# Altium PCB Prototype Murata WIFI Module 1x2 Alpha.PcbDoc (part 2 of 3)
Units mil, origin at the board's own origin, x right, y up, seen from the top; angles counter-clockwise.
Board outline 708.66 x 1594.49 mil, 6 copper layers (Component Side, Ground Plane (GND), Inner Layer 1, Inner Layer 2, Power Plane (VCC), Solder Side), stack 20.279 mil thick; 197 components, 116 nets, 943 pads, 479 vias.
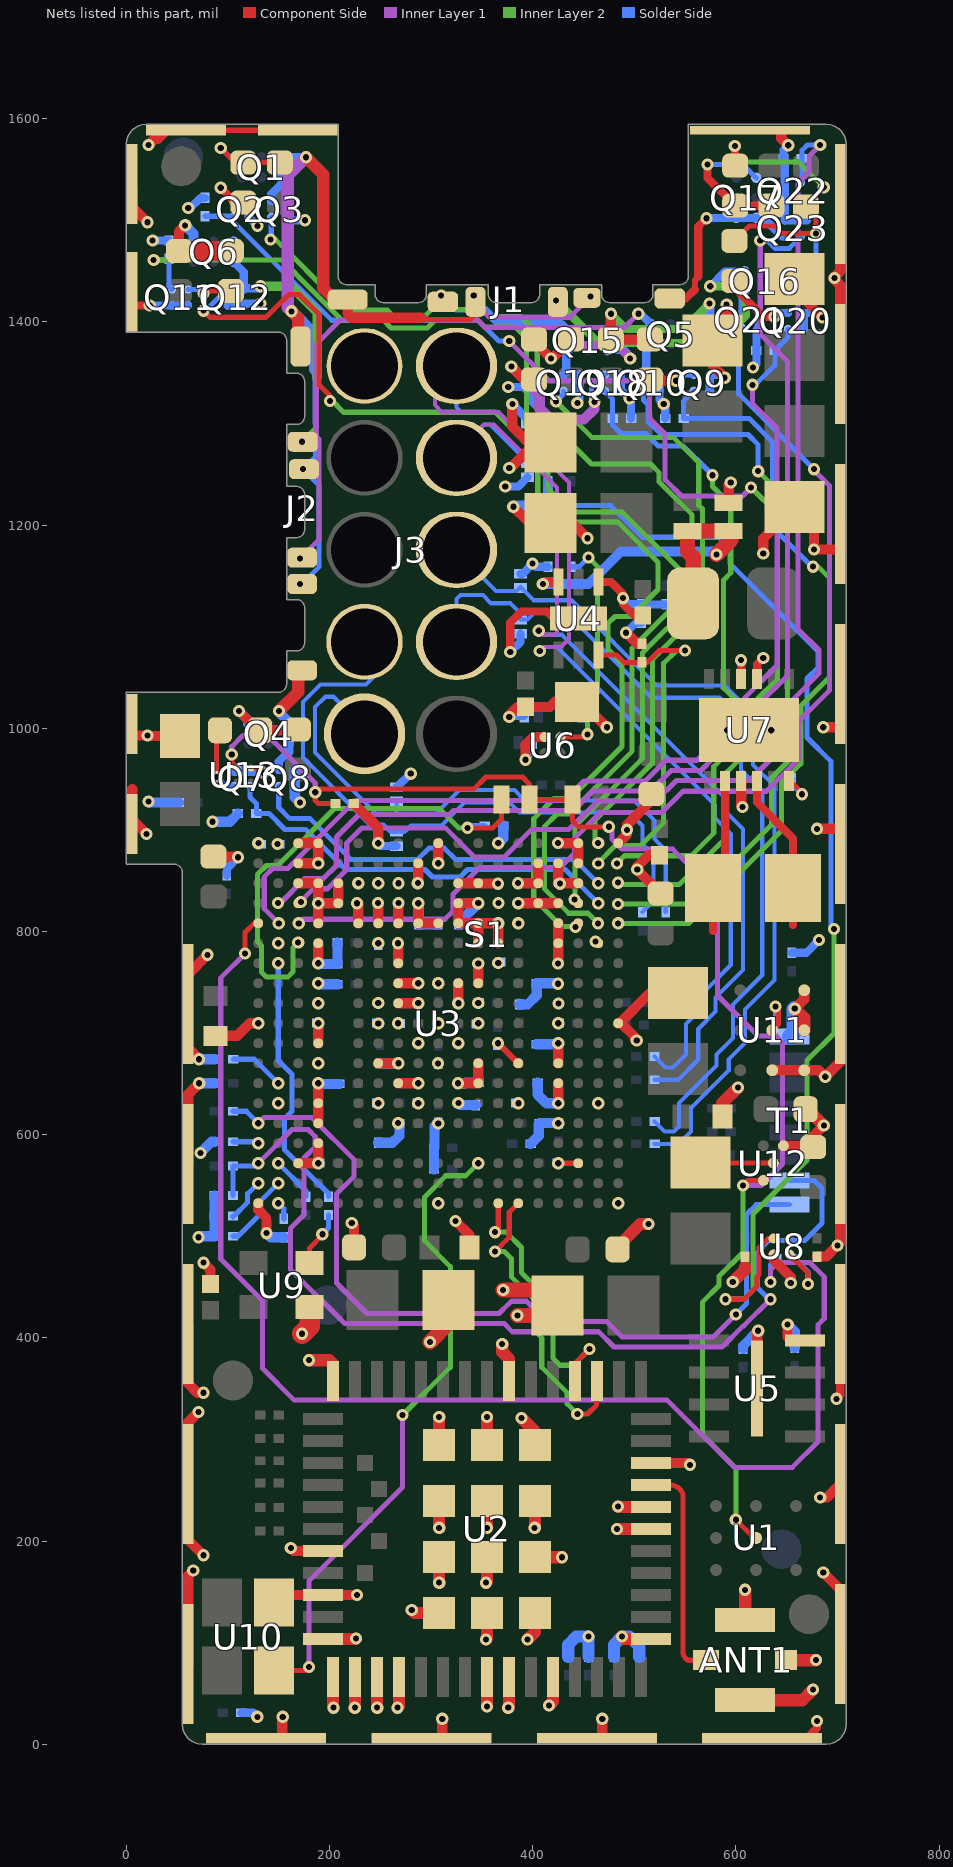
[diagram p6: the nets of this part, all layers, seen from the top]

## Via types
v1: diameter 12, hole 6, Component Side to Solder Side, tented both sides, 479 vias

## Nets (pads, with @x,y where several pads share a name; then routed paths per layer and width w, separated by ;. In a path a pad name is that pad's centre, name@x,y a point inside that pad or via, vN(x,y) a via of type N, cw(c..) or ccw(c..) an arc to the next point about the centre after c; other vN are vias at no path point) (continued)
C_RX_N: C49.1 J3.2 TVS6.1 | length 603.7
  Solder Side w4: J3.2@234.53,994.4 234.53,1000.47 204,1031 196,1031 186,1021 186,976 238.5,923.5 246,916 266,916 ; TVS6.1@266,928.01 266,916 ; C49.1@531,819.06 531,879.97 520,890.97 520,909 500,929 392,929 382,939 328,939 305,916 266,916
C_RX_P: C48.1 J3.4 TVS5.1 | length 653
  Solder Side w4: J3.4@234.53,1084.95 244,1075.47 244,1051 236,1043 191.03,1043 174,1025.97 174,971.03 240.03,905 253,905 260.01,897.99 TVS5.1@266,897.99 273.99,897.99 280.01,904.01 ; 280.03,904 309.97,904 332.97,927 377.03,927 387.03,917 495.03,917 508,904.03 508,886 519,875 519,830 C48.1@508.06,819.06
C_TX_CLK_N: C47.1 J3.7 R15.1 R37.1 TVS4.1 | length 1105.7
  Inner Layer 1 w4: J3.7@325.08,1266.05 325.08,1272.08 352,1299 362.03,1299 424,1237.03 424,1094 ; v1(406,1096) 410,1092 422,1092 424,1094 ; 424,1162 424,1094
  Solder Side w4: J3.7@325.08,1266.05 325.08,1272.08 352,1299 358,1299 395,1262 TVS4.1@395,1260.99 414.93,1260.99 R37.1@415,1261.06 R15.1@438,1261.06 ; v1(406,1096) 410,1092 428.97,1092 591.49,929.49 591.49,916.49 607,900.97 607,762.03 580,735.03 580,721 563,704 563,674 543,654 525.94,654 C47.1@519.91,654
C_TX_CLK_P: C46.1 J3.9 R36.1 R62.1 TVS3.1 | length 1115
  Inner Layer 1 w4: J3.9@325.08,1356.6 304,1335.53 304,1318 311,1311 367,1311 436,1242 436,1088 428,1080 411,1080 v1(407,1076)
  Solder Side w4: J3.9@325.08,1356.6 325.08,1315.92 330,1311 362.97,1311 387.96,1286.01 TVS3.1@395,1286.01 404.93,1286.01 406,1284.94 R62.1@415,1284.94 R36.1@438,1284.94 ; v1(407,1076) 411,1080 424,1080 579.49,924.51 579.49,911.51 583,908 595,896 595,767 568,740 568,725.97 551,708.97 551,678.97 538.03,666 530.91,666 C46.1@519.91,677
C_TX_N: C45.1 J3.3 TVS2.1 | length 857.4
  Solder Side w4: J3.3@325.08,1084.95 325.08,1127.08 329,1131 351,1131 359,1123 378,1123 388,1113 TVS2.1@388,1106.99 394.99,1106.99 402,1114 433.03,1114 517.03,1030 584,1030 605,1009 605,959 626,938 626,756.97 597,727.97 597,695 581,679 581,668 544,631 544,607.97 539.03,603 530,603 C45.1@520,613
C_TX_P: C43.1 J3.5 TVS1.1 | length 857.6
  Solder Side w4: J3.5@325.08,1175.5 325.08,1173.92 364,1135 383.99,1135 388,1139.01 401.01,1126 438,1126 522,1042 588.97,1042 617,1013.97 617,963.97 638,942.97 638,752 609,723 609,690.03 593,674.03 593,663.03 556,626.03 556,603 544,591 C43.1@520.09,591
CLK_19P2MHZ: R52.2 U3.N18 | length 256.2
  Solder Side w5: v1(149.61,768.7) 149.61,672.99 163.11,659.49 163.11,623 155.79,615.69 155.79,585.1 182.72,558.17 182.83,558.17 199,542 R52.2@199,539.06
CLK_REQ: U2.4 U3.A7 | length 267.2
  Component Side w5: v1(363,504) 366.14,507.14 U3.A7@366.14,532.48 ; U2.4@442,357.28 U2.4@441.61,357.67 441.61,374.61 v1(456,389)
  Inner Layer 2 w5: v1(363,504) 374,504 389,489 389,464.14 416.5,436.64 416.5,422.65 420,419.15 420,380 427,373 440,373 v1(456,389)
DETECT_RX: R69.2 U3.R19 | length 1336.2
  Component Side w5: v1(116.85,778.15) 116.85,798.85 126.07,808.07 U3.R19@129.92,808.07
  Inner Layer 1 w5: v1(116.85,778.15) 93,754.3 93,477.57 134,436.57 134,370 165,339 532,339 598.5,272.5 655.5,272.5 681,298 681,413 687,419 687,460 673,474 641,474 634,467 v1(634,455) v1@634,454
  Solder Side w5: v1@634,454 v1(634,455) 634,472.06 R69.2@639.94,478
DONE: R34.1 T1.8 U3.E19 | length 855.2
  Inner Layer 1 w5: v1(129.92,611.22) 135.6,616.9 182.7,616.9 224.3,575.3 224.3,559 207,541.7 207,454 237,424 367,424 376.5,433.5 ; 376.59,433.5 379.09,436 393.86,436 413.86,416 473,416 488,401 578,401 v1(600,423)
  Solder Side w5: R34.1@105.06,623 118.14,623 v1(129.92,611.22) ; v1(600,423) 610.5,433.5 610.5,521.5 620.1,531.1 T1.8@652.76,531.1
EN_32KHZ_CLK: U3.C8 U10.1 | length 633.3
  Component Side w5: U10.1@145.59,72.54 176.54,72.54 v1(180,76)
  Inner Layer 1 w5: v1(180,76) 180,161 272,253 v1(272,324)
  Inner Layer 2 w5: v1(272,324) 319,371 319,470 293.5,495.5 293.5,538.5 314.5,559.5 334.11,559.5 v1(346.46,571.85)
EPM_HBA_N: Q3.1 U3.T3 | length 1040.2
  Component Side w5: U3.T3@441.67,830.97 U3.T3@444.88,827.76
  Inner Layer 2 w5: v1(142,1480.92) 147.23,1480.92 177,1451.14 177,1451 216.5,1411.5 257.27,1411.5 264.77,1404 292.19,1404 300.19,1412 349.96,1412 356.96,1405 389,1405 404.5,1389.5 404.5,1313.5 458,1260 516,1260 524.5,1251.5 524.5,1242.41 532.41,1234.5 532.5,1234.5 557,1210 557,1123 508,1074 508,970 441.67,903.67 441.67,831 v1(441.2,831.44)
  Solder Side w5: v1(142,1480.92) 142.08,1480.92 142.72,1480.28 142.72,1488.85 ; Q3.1@142.72,1502.56 Q3.1@142.72,1503.13 ; 142.75,1488.88 142.75,1502.53 Q3.1@142.72,1503.13
EPM_HBA_P: Q2.1 R12.1 U3.U1 | length 1201.3
  Inner Layer 1 w5: v1(377,1381) 416,1342 503,1342 515,1330 515,1305 530.45,1289.55 530.45,1244.55 546.5,1228.5 606.5,1228.5 v1(615,1237)
  Inner Layer 2 w5: v1(484,848) 486,846 544,846 591,893 591,956.66 621.34,987 621.34,1028.7 640.82,1048.18 640.82,1211.18 v1(615,1237)
  Solder Side w5: R12.1@77.38,1503.94 104.06,1503.94 Q2.1@104.88,1503.13 104.88,1498.94 202.22,1401.6 346.22,1401.6 366.82,1381 v1(377,1381)
EPM_HBB_N: Q8.1 U3.U2 | length 375.6
  Solder Side w5: Q8.1@150.13,943.13 150.13,921.87 161,911 181,911 221,871 287,871 298,882 313,882 324,871 441.01,871 v1(464.57,847.44)
EPM_HBB_P: Q7.1 R41.1 U3.T2 | length 408.6
  Solder Side w5: Q7.1@121.87,943.13 121.87,932.18 128.06,926 R41.1@128.06,916 140.67,916 156.33,900.34 176.66,900.34 216.03,860.97 222.79,860.97 ; 222.81,861 294,861 301.37,853.63 328.63,853.63 336,861 432.09,861 440.5,852.59 ; 440.5,851.82 v1(464.57,827.76)
EPM_HBC_N: Q10.1 U3.T1 | length 725.8
  Inner Layer 2 w5: v1(484,827) 557,827 635,905 635,951 650.82,966.82 650.82,1224.18 v1(622,1253)
  Solder Side w5: Q10.1@509.13,1332.13 509.13,1323 513.37,1318.75 513.37,1302.12 526.49,1289 612,1289 622,1279 v1(622,1253)
EPM_HBC_P: Q9.1 R42.1 U3.R1 | length 754.7
  Inner Layer 2 w5: v1(484.2,808) 554,808 645,899 645,946 664,965 664,1022 692,1050 692,1148 681,1159 v1(676,1159)
  Solder Side w5: Q9.1@558.53,1332.13 548.66,1322.25 548.66,1318.34 R42.1@548.66,1305 612.86,1305 635.93,1281.93 635.93,1197.98 v1@674.91,1159
EPM_HBD_N: Q12.1 U3.R3 | length 1129.9
  Component Side w5: v1(76,1411) 82.5,1404.5 137.59,1404.5 145.5,1412.41 160.09,1427 170,1427 189.62,1407.38 189.62,1338 200.5,1327.13 v1(200.5,1322)
  Inner Layer 2 w5: v1(200.5,1322) 203,1322 213.95,1311.05 255.67,1311.05 255.72,1311 303.89,1311 303.94,1311.05 363.45,1311.05 405,1269.5 405,1231 433,1203 483.86,1203 522.93,1163.93 522.93,1163.73 523.5,1163.16 523.5,1136.5 497,1110 481,1110 474,1103 474,1078 488,1064 488,982 436.87,930.87 421,930.87 401.08,910.95 401.08,832.43 428.51,805 v1@442.28,805
  Solder Side w5: v1@78.09,1411 98.97,1431.87 Q12.1@99.89,1431.87
  other v1: 442.28,804.44
EPM_HBD_P: Q11.1 R44.1 U3.R2 | length 1214.7
  Inner Layer 2 w5: v1(27,1461) 153,1461 167,1447 167,1446.86 212.35,1401.5 253.12,1401.5 260.63,1394 296.34,1394 304.34,1402 345.82,1402 352.82,1395 383,1395 394,1384 394,1326 394,1297 415,1276 415,1235.91 437.91,1213 488,1213 544,1157 544,1125 498,1079 498,977.44 436.06,915.5 424,915.5 411.51,903.01 411.51,842 435.56,817.94 454.4,817.94 v1(464.34,808)
  Solder Side w5: v1(27,1461) 41.06,1461 R44.1@42,1461.94 42,1435.01 Q11.1@45.14,1431.87
EPM_HBE_N: Q19.1 U3.W2 | length 595.6
  Inner Layer 2 w5: v1(423.03,1321.53) 458.56,1286 539,1286 563.5,1261.5 563.5,1219.5 567,1216 567,1117 518,1068 518,976 518,965.86 461.5,909.36 v1@461.5,890.01
  Solder Side w5: v1(423.03,1321.53) 430.38,1328.87 Q19.1@430.38,1332.13
  other v1: 464.51,887
EPM_HBE_P: Q18.1 R59.1 U3.V1 | length 639.1
  Inner Layer 2 w5: v1(483,867) 490.5,874.5 556,874.5 578.25,896.75 578.25,962.21 606,989.96 606,1021.34 588,1039.34 588,1146 595,1153 595,1220 577,1238 v1(577,1249)
  Solder Side w5: Q18.1@471.29,1332.13 471.29,1331.56 478.79,1324.06 R59.1@478.79,1305 478.79,1298.21 487,1290 511.35,1290 523.58,1277.77 548.32,1277.77 v1@573,1253.09
EPM_HBF_N: Q21.1 U3.R17 | length 1051.2
  Inner Layer 1 w5: v1(169.77,808) 173.77,812 313.59,812 321.59,820 321.59,836.59 348,863 427,863 441,877 441,891.18 466.82,917 527,917 548,938 630,938 662,970 662,1007 692,1037 692,1239 v1@677,1254
  Solder Side w5: Q21.1@606.44,1393.97 602.77,1390.3 602.77,1329.23 v1(677,1255)
EPM_HBF_P: Q20.1 R60.1 U3.R18 | length 1019.8
  Inner Layer 1 w5: v1(150.07,808) 135.86,822.21 135.86,853.77 144.05,861.95 158.95,861.95 226,929 431.44,929 450.64,948.2 511,948.2 531.3,968.5 561.5,968.5 574.7,981.7 594.3,981.7 609.16,996.56 609.16,1030.46 640.5,1061.8 640.5,1295.77 616.27,1320 v1(616.27,1338)
  Solder Side w5: v1(616.27,1338) 619.09,1338 638.37,1357.28 R60.1@638.37,1371.84 651.32,1384.79 Q20.1@651.32,1393.13
EPM_HBG_N: Q23.1 U3.T18 | length 1117.1
  Inner Layer 1 w5: v1(149.36,828) 151.73,828 175.73,852 194,852 207,865 207,893 229,915 318,915 322,919 440.14,919 459.34,938.2 516,938.2 536.3,958.5 565.64,958.5 578.14,971 602.11,971 621.11,990 621.11,1022.11 651,1052 651,1360.86 624,1387.86 v1(624,1480)
  Solder Side w5: v1(624,1480) 631,1480 638.66,1472.34 652.66,1472.34 663.87,1483.56 Q23.1@663.87,1484.13
EPM_HBG_P: Q22.1 R61.1 U3.T17 | length 1254.9
  Inner Layer 1 w5: v1(171.82,829) 171.82,829.69 184.13,842 198.14,842 217,860.86 217,887 232,902 314,902 342.64,873.36 372,873.36 399.14,900.5 435.78,900.5 463.48,928.2 521.2,928.2 541.5,948.5 613.5,948.5 652,987 652,1024 682,1054 682,1077 661,1098 661,1536 671.84,1546.84 671.84,1562.84 v1(683,1574)
  Solder Side w5: Q22.1@663.87,1536.87 665.06,1538.06 R61.1@665.06,1561 665.06,1568.94 665.29,1568.94 670.34,1574 v1(683,1574)
EPM_REG_EN: R16.1 U3.V2 U4.6 | length 357.1
  Component Side w5: U4.6@464.69,1072.17 482.83,1072.17 490.11,1064.89 R16.1@507.63,1064.89 512.94,1064.89 524.62,1076.57 v1(550,1076.57)
  Inner Layer 2 w5: v1@464.57,867.66 481.41,884.5 506.5,884.5 529,907 529,1064 541.57,1076.57 v1(550,1076.57)
  other v1: 464.57,867
EPMA: J1.0 J2.0 Q1.4 Q1.5 Q3.4 | length 1019.4
  Component Side w5: 290.5,1404 292.3,1402.21 338.61,1402.21 343.72,1407.32 J1.0@343.72,1419.71
  Component Side w10: J1.0@205.2,1421.8 J1.0@216.22,1421.8 ; J1.0@217.94,1421.8 217.94,1408.07 222,1404 290.5,1404
  Component Side w12: v1(162.55,1410.36) 169.29,1403.62 J2.0@169.29,1375.74 ; v1(177,1562) 194,1545 194,1433 J1.0@203.77,1423.23
  Inner Layer 1 w5: v1(342,1426) 342,1419.96 357.46,1404.5 436.5,1404.5 v1(457,1425)
  Inner Layer 1 w12: v1(162.55,1410.36) 159,1413.91 159,1544 v1(177,1562)
  Solder Side w5: v1@173,1142 189.53,1158.53 189.53,1239.47 v1(174,1255) 186.5,1267.5 186.5,1299.5 186,1300 186,1353
  Solder Side w8: Q3.4@142.72,1518.87 142.72,1525.72 152.81,1535.81 Q1.4@152.81,1542.28 Q1.5@152.81,1561.97 v1(177,1562)
  Solder Side w12: v1(162.55,1410.36) 186,1386.91 186,1353
  other v1: 171,1142
EPMB: J2.3 Q4.4 Q4.5 Q8.4 | length 114.4
  Component Side w12: v1(150.47,1016.86) 169.29,1035.68 J2.3@169.29,1058
  Solder Side w8: Q8.4@150.13,958.87 150.13,967.13 159.69,976.69
  Solder Side w10: v1@150,1016.39 159.69,1006.7 Q4.5@159.69,1004.53 Q4.4@159.69,984.84 159.69,976.69
EPMC: J2.2 Q5.4 Q5.5 Q10.4 | length 624.9
  Inner Layer 1 w5: v1(171,1167) 189.53,1185.53 189.53,1284.69 187,1287.22 187,1378 211,1402 345.82,1402 353.32,1394.5 490.5,1394.5 v1(504,1408)
  Solder Side w8: v1(504,1408) 506.24,1408 Q5.4@516.4,1397.84 Q5.5@516.4,1378.16 511.84,1373.6 511.84,1366 511.84,1350.59 Q10.4@509.13,1347.87
EPMD: J2.1 Q6.4 Q6.5 Q12.4 | length 267.5
  Inner Layer 2 w5: v1(173,1282) 173,1282.31 187,1296.31 187,1344.38
  Inner Layer 2 w9: v1(132,1435) 161.89,1435 187.62,1409.26 187.62,1345
  Solder Side w8: Q6.5@105.6,1478.84 Q6.4@105.6,1459.16 115.63,1449.12 Q12.4@115.63,1431.87 116.76,1433 130,1433 v1(132,1435)
EPME: J1.1 Q15.4 Q15.5 Q19.4 | length 184.2
  Solder Side w5: v1(310,1426) 324.4,1411.6 353.4,1411.6
  Solder Side w8: 353.4,1411.6 367,1398 428.22,1398 Q15.4@434.38,1391.84 Q15.5@434.38,1372.16 433.09,1370.87 433.09,1350.59 Q19.4@430.38,1347.87
EPMF: J1.2 Q16.4 Q16.5 Q21.4 | length 352.9
  Inner Layer 2 w8: v1(423,1421) 465,1379 583,1379 610,1406 610,1422 597,1435 v1(574.81,1435)
  Solder Side w8: v1(574.81,1435) 589.49,1449.68 Q16.4@608.63,1449.68 Q16.5@608.63,1430 606.44,1427.81 Q21.4@606.44,1409.72
EPMG: J1.3 Q17.4 Q17.5 Q23.4 | length 187.9
  Component Side w6: 559.81,1432 559.81,1441.21 563,1444.41
  Component Side w8: J1.3@534.96,1423.23 551.03,1423.23 559.81,1432 ; 563,1444.41 563,1494 v1(571,1502)
  Solder Side w8: v1(571,1502) 571.31,1502.31 Q17.4@600.51,1502.31 Q17.5@620.19,1502.31 627.25,1502.31 645.44,1484.13 Q23.4@648.13,1484.13
EXO_DETECT_RX: R66.2 U8.A1 | length 1111.9
  Component Side w5: v1(589.96,438) 591,438 608,438 621,451 621,460.38 623,462.38 623,489 631.87,497.87 U8.A1@637.13,497.87
  Inner Layer 2 w5: v1(589.96,438) 608,438 617,447 617,522 670,575 670,673.09 696.5,699.59 v1(696.5,802.5)
  Solder Side w5: R66.2@438,1219.06 476.94,1219.06 508,1188 583.09,1188 594.5,1176.59 594.5,1162 681.11,1075.39 681.11,1060.11 670,1049 670,991 693.5,967.5 693.5,805.5 v1(696.5,802.5)
EXO_WAKE_RX: R65.2 U6.A1 | length 231.7
  Component Side w5: U6.A1@427.47,991.37 450.37,991.37 454,995 v1(454,994)
  Inner Layer 2 w5: v1(454,994) 454,1025 464,1035 464,1159 v1(455,1168)
  Solder Side w5: R65.2@438,1158.94 445.94,1158.94 v1(455,1168)
GND: ANT1.2 ANT1.3 ANT1.4 C1.1 C2.1 C3.1 C4.1 C5.1 C6.1 C7.1 C9.1 C10.1 C11.1 C12.2 C13.2 C14.2 C15.2 C16.1 C17.2 C18.1 C19.1 C20.1 C21.1 C22.1 C23.1 C24.1 C25.1 C26.1 C27.1 C28.1 C29.1 C30.1 C31.1 C32.1 C33.1 C34.1 C35.1 C36.1 C37.1 C38.1 C39.1 C40.1 C41.1 C42.1 C44.1 C50.1 C51.1 C52.1 C55.1 C56.1 C57.1 C58.1 C59.1 C60.1 C61.1 C62.1 C63.1 C64.1 C65.1 C66.1 C67.1 C68.1 C69.1 C70.1 C71.1 C72.1 C73.1 C74.1 C75.1 C77.1 C78.1 C81.1 C82.1 C94.1 C95.1 D2.1 J3.10 Q2.2 Q2.3 Q3.2 Q3.3 Q7.2 Q7.3 Q8.2 Q8.3 Q9.2 Q9.3 Q10.2 Q10.3 Q11.2 Q11.3 Q12.2 Q12.3 Q18.2 Q18.3 Q19.2 Q19.3 Q20.2 Q20.3 Q21.2 Q21.3 Q22.2 Q22.3 Q23.2 Q23.3 R10.1 R12.2 R14.2 R16.2 R20.1 R21.2 R23.2 R24.2 R25.2 R30.2 R32.2 R33.2 R37.2 R41.2 R42.2 R44.2 R47.2 R59.2 R60.2 R61.2 R62.2 R63.1 R67.2 R68.2 S1.S T1.1 TVS1.2 TVS2.2 TVS3.2 TVS4.2 TVS5.2 TVS6.2 TVS7.2 TVS8.2 TVS9.2 U2.7 U2.15 U2.22 U2.24 U2.26 U2.27 U2.28 U2.29 U2.30 U2.34 U2.35 U2.37 U2.42 U2.47 U2.48 U2.50 U2.53 U2.54 U2.55 U2.56 U2.57 U2.58 U2.59 U2.60 U2.61 U2.62 U2.63 U2.64 U3.A1 U3.A10 U3.A19 U3.C3 U3.C4 U3.C16 U3.C17 U3.D16 U3.E4 U3.E10 U3.E12 U3.E16 U3.F2 U3.F4 U3.F6 U3.F9 U3.F11 U3.F13 U3.F16 U3.F18 U3.G4 U3.G8 U3.G9 U3.G11 U3.G12 U3.G16 U3.H4 U3.H6 U3.H8 U3.H10 U3.H12 U3.H13 U3.H16 U3.J4 U3.J7 U3.J9 U3.J11 U3.J16 U3.K1 U3.K4 U3.K8 U3.K10 U3.K12 U3.K13 U3.K16 U3.K19 U3.L4 U3.L8 U3.L9 U3.L11 U3.L12 U3.L13 U3.L16 U3.M4 U3.M8 U3.M9 U3.M10 U3.M11 U3.M12 U3.M16 U3.N4 U3.N7 U3.N8 U3.N12 U3.N16 U3.P2 U3.P4 U3.P7 U3.P8 U3.P12 U3.P13 U3.P16 U3.P18 U3.R4 U3.R6 U3.R7 U3.R8 U3.R9 U3.R10 U3.R11 U3.R12 U3.R13 U3.R14 U3.R16 U3.T4 U3.T5 U3.T6 U3.T7 U3.T8 U3.T9 U3.T11 U3.T12 U3.T13 U3.T14 U3.T15 U3.T16 U3.U3 U3.U4 U3.U5 U3.U6 U3.U7 U3.U8 U3.U9 U3.U11 U3.U12 U3.U13 U3.U14 U3.U15 U3.U16 U3.U17 U3.V3 U3.V4 U3.V5 U3.V10 U3.V11 U3.V16 U3.V17 U3.W1 U3.W3 U3.W4 U3.W7 U3.W10 U3.W13 U3.W16 U3.W17 U3.W19 U4.7 U5.4 U5.9 U6.B1 U7.3 U7.9 U7.10 U7.13 U8.B1 U9.2 U10.2 U11.B1 U11.C1 U11.C2 U11.C3 U12.A3 U13.B1 | length 7473.4
  Component Side w5: S1.S@59.06,1588.58 S1.S@169.29,1588.58 ; U13.B1@122.89,960.89 123.07,960.7 128.3,960.7 v1@133.98,955.02 ; v1(425.2,571.85) U3.C3@444.88,571.85
  Component Side w5.5: v1(366,847) 366,847.3 U3.U7@366.14,847.44 ; v1(366.04,689.96) U3.J7@366.14,689.96 U3.H6@385.83,670.28
  Component Side w8: S1.S@5.91,1416.13 v1(23.13,1416.13) ; v1(378,1075) 378,1104 389,1115 414,1115 421,1108 U4.7@445,1108 ; v1(605,1067) 605.32,1066.68 U7.10@605.32,1048.23 ; U7.9@621.06,1048.23 621.06,1063.06 v1(627,1069) ; S1.S@625.99,5.91 669.91,5.91 680,16 v1(680,23) ; v1@651.39,1574 v1(651.56,1573.83) ; v1(699,340) 702.76,343.76 S1.S@702.76,413.39
  Component Side w10: 5.91,939.96 5.91,910.09 v1(20,896) ; S1.S@5.91,993 v1(21,993) 21.54,992.46 C95.1@53,992.46 ; S1.S@5.91,1531.91 5.91,1513.09 v1(21,1498) ; v1(22,1574) 28.21,1580.21 31,1580.21 S1.S@39.37,1588.58 ; S1.S@61.02,78.74 61.02,166.02 v1(66,171) ; S1.S@61.02,413.39 61.02,354.98 70,346 v1(76,346) ; S1.S@61.02,570.87 61.02,639.83 v1(71.78,650.59) ; v1(71,327) 61.02,317.02 S1.S@61.02,255.91 61.02,200.98 v1(76,186) ; v1(71.76,674.21) 61.02,684.95 S1.S@61.02,728.35 61.02,758.02 v1(80,777) ; v1(76,474) 83,467 C57.1@83,452.99 ; C60.1@85.91,873.68 109.32,873.68 v1(110,873) ; C16.1@88,697.32 109.32,697.32 121.65,709.65 v1(129.92,709.65) ; U3.A19@129.92,532.48 129.92,526.08 137.5,518.5 ; v1(138,503) 138,515.5 ; U10.2@145.59,139.46 153.17,147.04 U2.24@193.58,147.04 v1(227,147) v1(227,147) ; S1.S@153.55,5.91 153.55,26.55 v1(154,27) ; v1(162,193) 164.65,190.35 U2.22@193.58,190.35 ; U3.V17@169,867.42 U3.V17@169.29,867.13 U3.V16@188.98,867.13 ; U3.W17@169.19,886.81 U3.W17@169.29,886.81 U3.W16@188.98,886.81 U3.V16@188.98,867.13 ; U3.C17@169.29,571.85 v1(188.98,571.85) U3.D16@188.98,591.54 ; U3.U17@169.29,847.44 U3.U16@188.98,847.44 v1(188.98,827.76) ; U3.E16@188.98,611.22 U3.F16@188.98,630.91 v1(188.98,650.59) ; U3.J16@188.98,689.96 v1(188.98,709.65) ; v1(188.98,768.7) U3.P16@188.98,788.39 ; U3.R16@188.98,808.07 v1(188.98,827.76) ; v1(188.98,867.02) U3.V16@188.98,867.13 ; U3.U15@208.72,847.5 U3.U15@208.66,847.44 U3.T15@208.66,827.76 v1(188.98,827.76) ; v1(222,513) 224.32,510.68 C59.1@224.32,489 ; R47.2@224.06,926 248.03,902.02 U3.W13@248.03,888.23 ; v1(227.24,827.76) U3.T14@228.35,827.76 U3.R14@228.35,808.07 ; U3.H13@248.03,670.28 U3.H12@267.72,670.28 ; U3.R13@248.03,808.07 U3.T13@248.03,827.76 v1(247.79,828) U3.T13@248.03,828.24 ; U3.G12@267.72,650.59 v1(287.41,650.59) ; U3.L12@267.72,729.33 U3.L11@287.4,729.33 ; U3.M12@267.72,749.02 v1(287.42,749) ; U3.N12@267.72,768.7 U3.P12@267.72,788.39 ; U3.R12@267.72,808.07 U3.T12@267.72,827.76 ; v1(287.4,827.76) U3.R11@287.4,808.07 U3.R10@307.09,808.07 ; U3.U11@287.4,847.44 U3.V11@287.4,867.13 ; U3.W10@307,886.9 U3.W10@307.09,886.81 v1(307.09,867.13) ; S1.S@311.03,5.91 v1(311,25) ; v1(324,515) 337.69,501.32 C37.1@337.69,489 ; U3.G9@326.77,650.59 U3.G8@346.46,650.59 ; U3.M9@326.77,749.02 v1(326.83,729.33) v1(326.83,729.33) ; U3.U9@326.77,847.44 U3.U8@346.46,847.44 346.6,847.3 U3.U7@366,847.3 ; U3.M8@346.46,749.02 v1(346.46,768.54) U3.N8@346.46,768.7 ; U3.G8@346.5,650.55 U3.G8@346.46,650.59 ; U3.H8@346.46,670.28 U3.H8@346.46,670.28 U3.G8@346.46,650.59 ; U3.P8@346.46,788.39 U3.P8@346.46,788.39 U3.R8@346.46,808.07 ; U3.R8@346.5,808.03 U3.R8@346.46,808.07 ; v1(346.5,827.8) v1(346.5,827.8) U3.T9@326.77,827.76 U3.R9@326.77,808.07 U3.R8@346.46,808.07 ; U3.P7@366.03,788.5 U3.P7@366.14,788.39 366.14,807.93 v1(366.07,808) U3.R7@366.14,808.07 U3.R8@346.46,808.07 ; v1(377,1011) 377,1012.92 385.08,1021.01 C2.1@393,1021.01 ; v1(377,1256) 378,1256 403,1281 C39.1@417.47,1281 396,1281 380,1297 v1(380,1319) ; v1(381,1218) C9.1@394,1205 ; U3.H6@385.83,670.28 U3.H6@386,670.45 ; v1(385.83,827.83) U3.T5@405.51,827.76 U3.T4@425.2,827.76 ; U3.U6@385.83,847.44 U3.U5@405.51,847.44 U3.V5@405.51,867.13 ; v1(393,969) 393,984 400.37,991.37 U6.B1@411.72,991.37 ; C2.1@396,1018.01 C2.1@393,1021.01 ; C9.1@417.39,1202 439,1202 v1(454,1187) ; v1(425.01,887) U3.W4@425.2,886.81 U3.W3@444.88,886.81 U3.V3@444.88,867.13 ; v1(425.2,630.91) U3.G4@425.2,650.59 ; U3.H4@425.2,670.28 v1(425.2,689.96) ; U3.N4@425.2,768.7 U3.P4@425.2,788.39 U3.R4@425.2,808.07 ; U3.V4@425.2,867.13 U3.U4@425.2,847.44 U3.U3@444.88,847.44 ; C52.1@431.19,1026 C52.1@443.54,1026 ; S1.S@468.51,5.91 v1(468.48,25) ; v1(473,1001) 448,1026 C52.1@443.54,1026 ; U3.A1@483.69,531.91 v1(484.25,532.48) ; U3.K1@484.25,709.65 U3.K1@485.67,709.65 ; U3.W1@484.25,886.81 493,895.56 v1@493,905 ; v1(492,1094) 503,1083 R16.2@507.63,1083 ; v1(493,900) v1@493,905 ; v1(502.47,692.67) 500.29,694.85 500.29,696.63 487.27,709.65 U3.K1@485.67,709.65 ; v1@502.75,860.75 C72.1@526,837.49 ; v1(503,861) 503,864 514.01,875.01 C77.1@525,875.01 ; U2.50@516.42,276.96 550.27,276.96 cw(c550.27,270.27) v1(555,275) ; C50.1@517,935.32 517,929 v1@493,905 ; C32.1@543,739.4 515.42,739.4 U3.K1@485.67,709.65 ; v1(589,1345) 577,1357 C10.1@577,1381.4 591,1395.4 v1(591,1417) ; v1(595,1242) 593,1240 593,1224.07 D2.1@595.29,1221.78 ; U7.3@605.32,947.84 605.32,923.68 v1(606.5,922.5) ; U5.9@621,350 621,406 v1(622,407) ; v1(627,1172) 627,1186.8 C40.1@657.8,1217.6 677,1198.4 v1(677,1176) 701,1176 702.76,1177.76 S1.S@702.76,1200.79 ; U11.B1@635.83,663.39 U11.C1@667.32,663.39 681.61,663.39 v1(688,657) 702.76,671.76 S1.S@702.76,728.35 S1.S@702.76,678 ; U8.B1@637.13,482.13 637.13,476.77 654,459.9 v1(654,454) ; S1.S@644.69,1587 644.69,1580.7 v1@651.39,1574 ; U12.A3@646.84,589.05 674.64,589.05 C82.1@676,587.68 676,598.4 v1(686.6,609) ; v1(651,413) 651,401 654.76,397.24 U5.4@668.24,397.24 ; C11.1@657.7,1442.4 657.7,1431.83 v1(685.34,1404.19) ; v1(658,724) 667.32,733.32 U11.C3@667.32,742.13 ; C41.1@680,479.94 688.94,479.94 v1(700,491) 702.76,493.76 S1.S@702.76,570.87 ; v1(680,901) 702.76,901 S1.S@702.76,885.83 ; v1(683,243) 689.85,243 S1.S@702.76,255.91 ; v1(686,169) 702.76,152.24 S1.S@702.76,98.43 ; v1(686,1001) 702.76,1001 S1.S@702.76,1043.31 ; v1@696.4,1443.6 702.76,1449.95 S1.S@702.76,1560.24 ; v1(697,1443) 696.4,1442.4 702.76,1436.05 S1.S@702.76,1358.27 ; C2.1@393,1021.01 417.01,1021.01 422,1026 C52.1@443.54,1026
  Component Side w12: v1(180,378) 200,378 203.43,374.57 U2.15@203.43,357.67 ; U2.26@193.58,103.73 225.73,103.73 v1(226,104) ; U2.27@203.43,66.33 203.43,36.57 v1(204,36) ; v1(225,36) 225.08,36.08 U2.28@225.08,66.33 ; U2.29@246.73,66.33 246.73,36.27 v1(247,36) ; v1(267,36) 268.39,37.39 U2.30@268.39,66.33 ; v1(281,132) 283.68,129.32 U2.58@307.76,129.32 ; U2.57@307.76,184.44 307.76,159.24 v1(308,159) ; U2.56@307.76,239.56 307.76,213.24 v1(308,213) ; U2.55@307.76,294.68 307.76,321.76 v1(308,322) ; v1(354,103) 355,104 U2.59@355,129.32 ; v1(354,159) 355,160 U2.64@355,184.44 ; v1(355,37) U2.34@355,66.33 ; v1(355,213) U2.63@355,239.56 ; U2.54@355,294.68 v1(355,322) ; v1(370,394) 370,386 376.65,379.35 U2.7@376.65,357.67 ; v1(376,36) 376.65,36.65 U2.35@376.65,66.33 ; v1(389,321) 402.24,307.76 U2.53@402.24,294.68 ; v1(395,103) 402.24,110.24 U2.60@402.24,129.32 ; v1(402,213) 402.24,213.24 U2.62@402.24,239.56 ; U2.61@402.24,184.44 402.69,184 v1(429,184) ; v1(416,38) 419.96,41.96 U2.37@419.96,66.33 ; v1(483,212) U2.47@516.42,212 ; C61.1@483.69,487 483.69,489.68 506,512 v1(514,512) ; v1(484,234) 484.35,233.65 U2.48@516.42,233.65 ; v1(488,106) 490.27,103.73 U2.42@516.42,103.73 ; C31.1@586.69,624.31 C31.1@586.69,618 586.69,631.07 v1(602,646.39) ; v1(597,455) 609,467 609,470.04 ; v1(609,152) 609.25,151.75 ANT1.3@609.25,122.05 ; ANT1.4@609.25,43.31 665.31,43.31 v1(676,54) ; ANT1.2@649.61,82.68 678.68,82.68 v1(679,83) ; v1(658,724) 667.32,714.68 U11.C2@667.32,702.76 ; C81.1@670.69,625 670.69,624.92 v1(686.6,609)
  Component Side w15: v1(299,396) 317.4,414.4 C38.1@317.4,437 ; v1(371,447) 409.6,447 C78.1@424.6,432 414.6,422 v1(385,422)
  Component Side w20: v1(173,404) 180.56,411.56 U9.2@180.56,430.35
  Solder Side w6: v1(393,969) 398.3,974.3 TVS7.2@398.3,986
  Solder Side w8: v1(23.13,1416.13) Q11.2@45.14,1416.13 Q11.3@60.89,1416.13 ; v1(26,1480) 26.06,1480.06 R44.2@42,1480.06 ; v1(61,1512) 63,1512 73.06,1522.06 R12.2@77.38,1522.06 ; R63.1@99,855.06 99,862 v1(110,873) ; Q12.2@99.89,1416.13 Q12.3@115.63,1416.13 117.51,1418 v1(132,1418) ; C1.1@113.06,31 125,31 v1(129,27) ; Q2.3@120.63,1522.54 Q2.3@120.63,1518.87 Q2.2@120.63,1503.13 v1(129.25,1494.5) v1@128.41,1494.5 ; Q3.3@158.47,1518.87 Q3.2@158.47,1503.13 161.59,1500 v1(176,1500) ; v1(248,886.84) 250.83,884.01 TVS5.2@266,884.01 ; TVS6.2@266,941.99 266.69,941.99 v1(280,955.3) ; v1(373,1238) 385.99,1238 TVS4.2@395,1247.01 ; v1(376,1336) 391,1336 398,1329 398,1323 415,1306 R62.2@415,1303.06 ; v1(377,1011) 378,1012 TVS8.2@391.63,1012 ; v1(378,1075) 388,1085 TVS2.2@388,1093.01 ; v1(380,1319) 395,1304 TVS3.2@395,1299.99 ; TVS1.2@388,1151.99 389.99,1151.99 v1(400,1162) 403.06,1158.94 R67.2@415,1158.94 ; v1(444,1320) 446,1322 446,1332 Q19.2@446.12,1332.13 Q19.3@446.12,1347.87 ; TVS9.2@448.67,1012 462,1012 v1(473,1001) ; Q18.3@487.03,1347.87 Q18.2@487.03,1332.13 487.86,1332.13 v1(495.46,1324.53) 496.9,1323.09 R59.2@496.9,1305 ; v1(492,1094) 501.94,1103.94 R14.2@507,1103.94 ; Q10.3@524.87,1347.87 Q10.2@524.87,1332.13 524.87,1323.13 v1(529,1319) 530.54,1317.46 R42.2@530.54,1305 ; Q9.2@574.28,1332.13 Q9.3@574.28,1347.87 v1@586.13,1347.87 ; v1(617,1355) 620.26,1358.26 R60.2@620.26,1371.84 620.26,1392.04 Q21.2@622.19,1393.97 Q21.3@622.19,1409.72 ; v1(651.56,1573.83) 646.94,1569.22 R61.2@646.94,1561 648.13,1559.82 Q22.2@648.13,1536.87 Q22.3@648.13,1521.13 Q23.3@648.13,1499.87 Q23.2@663.87,1499.87 670.14,1499.87 ; R32.2@655,779.06 669.41,779.06 v1(681.91,791.55) ; Q20.2@667.06,1393.13 667.06,1408.72 680.81,1408.72 v1(685.34,1404.19)
  Solder Side w10: v1(22,928) 23,927 C94.1@51.94,927 ; v1(71,499) 72,500 R23.2@86.94,500 R24.2@86.94,520 C14.2@86.94,540 ; v1(71.76,674.21) R21.2@87.4,674.21 ; v1(71.78,650.59) R20.1@87.4,650.59 ; v1(73,582) 84,593 R30.2@86.94,593 ; v1(85,908) 101.94,908 R41.2@109.94,916 ; Q7.3@106.13,958.2 121.2,958.2 Q7.2@121.87,958.87 122.54,958.2 130.8,958.2 v1@131.84,957.16 ; v1(138,503) 142.06,498.94 R25.2@155,498.94 ; Q8.2@165.87,939.13 Q8.2@165.87,943.13 ; Q8.3@165.87,958.87 Q8.2@165.87,943.13 ; v1(171,927) 165.87,932.13 Q8.2@165.87,943.13 ; v1(188.98,650.59) 189.57,650 C18.1@209.94,650 ; v1(188.98,749.02) 189.99,748 C69.1@207.94,748 ; v1(188.98,768.7) 189.68,768 C28.1@207.94,768 C71.1@207.94,789 ; C68.1@248,591.94 261.94,591.94 268.94,598.94 C67.1@268.94,611 ; C5.1@249.51,670.19 267.69,670.19 v1(267.78,670.28) ; v1(287.4,827.76) 287.5,827.66 C29.1@287.5,807.06 C30.1@307,807.06 ; C26.1@302.94,566 C51.1@302.94,587 303.4,587.46 303.4,608.35 C36.1@307,611.94 ; v1(326.59,650.59) 333.59,650.59 334,651 C64.1@346.94,651 ; C33.1@327,807.06 327,808.3 v1(346.5,827.8) ; v1@328.81,629.06 C27.1@344,629.06 ; v1(366.14,886.86) 371.06,891.77 R10.1@371.06,904 ; v1(381,1218) 382.06,1219.06 R68.2@415,1219.06 R37.2@415,1242.94 ; C6.1@387,728.06 394.96,728.06 404.06,737.16 C24.1@404.06,749 424.5,749 v1(425,748.5) ; C73.1@398.06,591 406,598.95 406,610.24 C63.1@407.06,611.3 C17.2@425.51,611.3 ; C65.1@404.06,689 424.24,689 v1(425.2,689.96) ; C25.1@405.06,651 405.06,639.34 413.49,630.91 v1(425.2,630.91) ; C13.2@607,389.06 607,392 v1(622,407) ; v1(651,413) 658,406 C12.2@658,390.06
  Solder Side w12: C74.1@435,86.06 435,98 443,106 v1(455,106) C75.1@455,86.06 ; C56.1@480,86.06 480,98 v1(488,106) 495,106 505,96 C55.1@505,86.06
  Solder Side w15: T1.1@655.46,696.46 T1.1@652.76,696.46 657.5,701.2 657.5,723.5 v1(658,724)
  other v1: 307.09,532.48 267.68,611.26 307.09,611.09 425.2,611.22 149.61,630.91 248.03,630.91 287.4,630.91 326.87,631 385.91,630.91 464.57,630.91 188.98,670.28 307,670.19 287.44,690 326.81,690 248.03,709.53 267.65,709.65 307.09,709.59 346.5,709.6 425.2,709.65 188.98,729.33 248.03,729.47 287.4,729.4 346.46,729.46 425.5,729 307.07,749 425,768.5 366.14,768.86 149.61,788.39 248,788.42 267.61,788.39 462,790 385.9,808 267.96,828 366.39,828 248,847.47 267.94,847.44 427,847 228.41,847.5 287,847.5 385.5,847.5 130,886.89 135.09,956.12 591.54,998.03 634.84,998.03
HOST_WAKE: U2.3 U3.A6 | length 302.2
  Component Side w5: v1@363.09,485 377,498.91 377,523.65 U3.A6@385.83,532.48 ; v1(444,325) 454,325 463,334 463,357.4 U2.3@463.27,357.67
  Inner Layer 2 w5: v1(363,485) 372,485 379,478 379,460 401.5,437.5 401.5,407.5 409,400 409,371 434,346 434,335 v1(444,325)
INITN: R26.1 U3.C18 | length 44.7
  Solder Side w5: v1@150.15,571.85 v1(149.61,571.85) 177,544.46 R26.1@177,539.06
NetANT1_1: ANT1.1 U2.49 | length 221
  Component Side w5: U2.49@516.42,253.31 U2.49@518.11,255 ; U2.49@516.42,255.31 534.6,255.31 cw(c534.6,240.6) 545,251 cw(c537.76,243.76) 548,243.76 548,91.24 ccw(c558.24,91.24) 551,84 ccw(c554.19,87.19) 554.19,82.68 ANT1.1@570.87,82.68
NetC8_1: C8.1 R13.2 R14.1 U4.1 | length 107.7
  Component Side w8: U4.1@464.69,1143.83 477.17,1143.83 489,1132 v1(489,1128) 489,1122 499.99,1111.01 C8.1@508.42,1111.01
  Solder Side w8: v1(489,1128) 494.94,1122.06 R14.1@507,1122.06 507.11,1121.94 R13.2@531,1121.94
NetD1_1: D1.1 D2.2 L1.2 U4.3 | length 345.1
  Component Side w10: v1(410,1142) 411.83,1143.83 U4.3@425.32,1143.83
  Component Side w15: L1.2@558.01,1123 558.01,1168.44 552.45,1174 D1.1@552.45,1194.22 595.29,1194.22 595.29,1185.29 v1(581,1171)
  Solder Side w10: v1@412,1142 455,1142 487,1174 578,1174 v1(581,1171)
NetL5_1: L5.1 U12.B2 | length 72.2
  Component Side w5: L5.1@565,572.4 565.4,572 U12.B2@637,572
NetL6_1: L6.1 U7.2 | length 152.4
  Component Side w8: 577.63,800.37 L6.1@577.63,843 589.57,854.94 U7.2@589.57,947.84
NetL6_2: L6.2 U7.4 | length 156.1
  Component Side w8: U7.4@621.06,947.84 621.06,926.94 656.37,891.63 L6.2@656.37,843 656.37,806.37
NetQ1_1: Q1.1 R9.2 R11.1 | length 88.3
  Component Side w5: v1(93,1571) 107.32,1556.68 R11.1@115.17,1556.68 151,1556.68 R9.2@151.13,1556.81
  Solder Side w5: v1(93,1571) 102.03,1561.97 Q1.1@113.44,1561.97
NetQ2_4: Q2.4 R11.2 | length 46.7
  Component Side w8: v1(93,1532) 107.69,1517.31 R11.2@115.17,1517.31
  Solder Side w5: v1(93,1532) 93,1530 95,1528 95.75,1528 Q2.4@104.88,1518.87
NetQ4_1: Q4.1 R17.2 R35.1 | length 82.5
  Component Side w10: v1(111,1017) 130,998 R35.1@131.69,998 168.31,998 R17.2@169,998.69
  Solder Side w10: v1(111,1017) 120.32,1007.68 Q4.1@120.32,1004.53
NetQ5_1: Q5.1 R18.2 R38.1 | length 223.8
  Component Side w10: v1@476.9,1407.9 R18.2@476.9,1382.69 R38.1@513.57,1382.68
  Inner Layer 2 w8: v1(477,1408) 492,1393 549,1393 v1(574,1418)
  Solder Side w10: Q5.1@555.77,1378.16 557.46,1378.16 574,1394.7 v1(574,1418)
NetQ6_1: Q6.1 R19.2 R40.1 | length 94.4
  Component Side w10: R19.2@52.01,1469.69 52.01,1489.01 v1(58,1495)
  Component Side w20: R19.2@56,1469.69 R40.1@103,1469.68
  Solder Side w10: v1(58,1495) 66.23,1486.78 Q6.1@66.23,1478.84
NetQ7_4: Q7.4 R35.2 | length 68.2
  Component Side w5: v1(89,952) 89,974 89,994.69 R35.2@92.31,998
  Solder Side w5: v1(89,952) 97.87,943.13 Q7.4@106.13,943.13
NetQ9_4: Q9.4 R38.2 | length 49.1
  Component Side w10: R38.2@514.02,1347.31 519.33,1342 v1(541,1342)
  Solder Side w5: v1(541,1342) 546.87,1347.87 Q9.4@558.53,1347.87
NetQ11_4: Q11.4 R40.2 | length 39.2
  Component Side w5: v1(76,1428) 78.31,1430.31 R40.2@103,1430.31
  Solder Side w5: Q11.4@60.89,1431.87 v1@72.13,1431.87
NetQ15_1: Q15.1 R53.2 R56.1 | length 168.8
  Component Side w10: R56.1@401.41,1382.68 401.41,1380.59 v1(418,1364) 419.26,1364 R53.2@437.95,1382.69
  Inner Layer 1 w8: v1(418,1364) 431,1377 483,1377 v1(496,1364)
  Solder Side w8: Q15.1@473.75,1372.16 489.84,1372.16 496,1366 v1(496,1364)
NetQ16_1: Q16.1 R54.2 R57.1 | length 189.9
  Component Side w5: R57.1@598.6,1479.68 613.42,1494.5 638,1494.5 645.5,1487 v1(679,1487) 679,1503.31 R54.2@669,1513.31
  Solder Side w5: Q16.1@648,1430 679,1461 v1(679,1487)
NetQ17_1: Q17.1 R55.2 R58.1 | length 141.3
  Component Side w8: v1(572,1555) 572.2,1554.8 572.2,1541.5 R58.1@599.39,1514.32 R55.2@635,1514.31
  Solder Side w5: v1(572,1555) 606.88,1555 Q17.1@620.19,1541.68
NetQ18_4: Q18.4 R56.2 | length 179.5
  Component Side w10: v1(379,1356) 391.69,1343.31 R56.2@401.41,1343.31
  Inner Layer 1 w10: v1(379,1356) 407.03,1327.97 407.03,1314.9 417.93,1304 450.63,1304 461,1314.37 v1(461,1321)
  Solder Side w5: v1@458,1324 458,1335.15 470.72,1347.87 Q18.4@471.29,1347.87
NetQ20_4: Q20.4 R57.2 | length 74
  Component Side w8: R57.2@598.6,1440.31 598.6,1433.66 627.26,1405 v1(638,1405)
  Solder Side w8: v1(638,1405) 638,1407 639.87,1408.87 Q20.4@651.32,1408.87
NetQ22_4: Q22.4 R58.2 | length 157
  Component Side w8: R58.2@599,1554.08 v1(599,1573)
  Inner Layer 2 w5: v1(599,1573) 599,1562 603.5,1557.5 661.52,1557.5 v1(686.51,1532.51)
  Solder Side w5: Q22.4@663.87,1521.13 675.13,1521.13 v1(686.51,1532.51)
NetR21_1: R21.1 U3.G18 | length 53.9
  Solder Side w5: R21.1@105.51,674.21 125.98,674.21 v1(149.61,650.59)
NetR23_1: R23.1 U3.B18 | length 73.5
  Solder Side w5: R23.1@105.06,500 110,500 132,522 132,534.56 v1(149.61,552.17)
NetR24_1: R24.1 U3.B19 | length 43.1
  Solder Side w5: R24.1@105.06,519 R24.1@105.11,519 ; R24.1@105.06,520 106.11,520 119.56,533.44 119.56,541.8 v1(129.92,552.17)
NetR25_1: R25.1 U3.A18 | length 17.7
  Solder Side w5: v1(149.61,532.48) 155,527.09 R25.1@155,517.06
NetR30_1: R30.1 U3.D19 | length 25.5
  Solder Side w5: R30.1@105.06,593 128.46,593 v1(129.92,591.54)
NetR33_1: R33.1 U3.W18
  other v1: 149,886
NetR39_2: R39.2 U7.6 | length 39
  Component Side w5: U7.6@652.56,947.84 654.16,947.84 665,937 v1(665,935)
  Solder Side w5: R39.2@655,950.94 655,945 v1(665,935)
NetR52_1: R52.1 U9.3 | length 54.9
  Component Side w5: U9.3@180.56,473.65 180.56,488.47 193,500.91 v1(193,502)
  Solder Side w5: v1(193,502) 199,508 R52.1@199,520.94
NetR69_1: R69.1 U8.B2 | length 67
  Component Side w5: U8.B2@652.87,482.13 671,464 v1(671,453)
  Solder Side w5: R69.1@658.06,478 671,465.06 v1(671,453)
POWER_EN: D3.2 D4.2 R47.1 U1.B2 U11.B2 U12.C1 U13.B2 | length 1454.9
  Component Side w5: v1(103.83,974.2) 103.83,966.17 U13.B2@109.11,960.89 ; R47.1@205.94,926 189,926 186,929 v1(186,937) 189,940 342,940 354,952 390,952 396.78,945.22 D4.2@396.78,930 D3.2@439.22,930 439.22,908.78 445,903 v1(475,903) ; v1(600,221) 618,203 U1.B2@620,203 ; v1(606.97,550) 611.92,554.95 U12.C1@627.16,554.95 ; U11.B2@635.83,702.76 642,708.93 642,723 v1(639,726)
  Inner Layer 1 w5: v1(103.83,974.2) 103.83,981.83 115,993 139,993 186,946 v1(186,937) ; v1@478.01,899.99 478.01,891 488.01,881 538,881 582,837 582,737 622,697 639,697 ; v1(606.97,550) 625,550 646,571 646,690 639,697 ; v1(639,726) 639,697
  Inner Layer 2 w5: v1(600,221) 600,272 567,305 567,434.91 583.5,451.41 583.5,460.59 606.97,484.06 v1(606.97,550)
POWER_HOLD: D4.1 R10.2 U3.P17 | length 484.9
  Component Side w5: v1(336,902) 361,902 369.22,910.22 D4.1@369.22,930 D4.1@369.22,935
  Inner Layer 2 w5: v1(169.23,789) 164,783.77 164,760 159,755 138,755 133,760 133,786 129,790 129,856 138,865 149,865 205,921 308,921 327,902 v1(336,902)
  Solder Side w5: v1(336,902) 338,904 R10.2@352.94,904
PROGRAM_N: C14.1 R22.2 T1.7 U3.C19 | length 985.7
  Inner Layer 1 w5: v1(129.92,571.85) 163.11,605.04 178.96,605.04 186,598 186,588 175,577 175,521.09 161.5,507.59 161.5,467.5 215,414 372,414 380,406 465,406 480,391 586.38,391 607.19,411.81 607.81,411.81 v1(634,438)
  Solder Side w5: C14.1@105.06,540 R22.2@105.06,569 v1@127.07,569 ; v1(634,438) 632.62,438 621,449.62 621,484 633,496 668,496 685,513 685,547 677.28,554.72 T1.7@652.76,554.72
